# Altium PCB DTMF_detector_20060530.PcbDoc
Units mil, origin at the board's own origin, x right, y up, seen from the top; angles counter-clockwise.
Board outline 2118 x 2053 mil, 2 copper layers (Top Layer, Bottom Layer); 16 components, 31 nets, 85 pads, 0 vias.
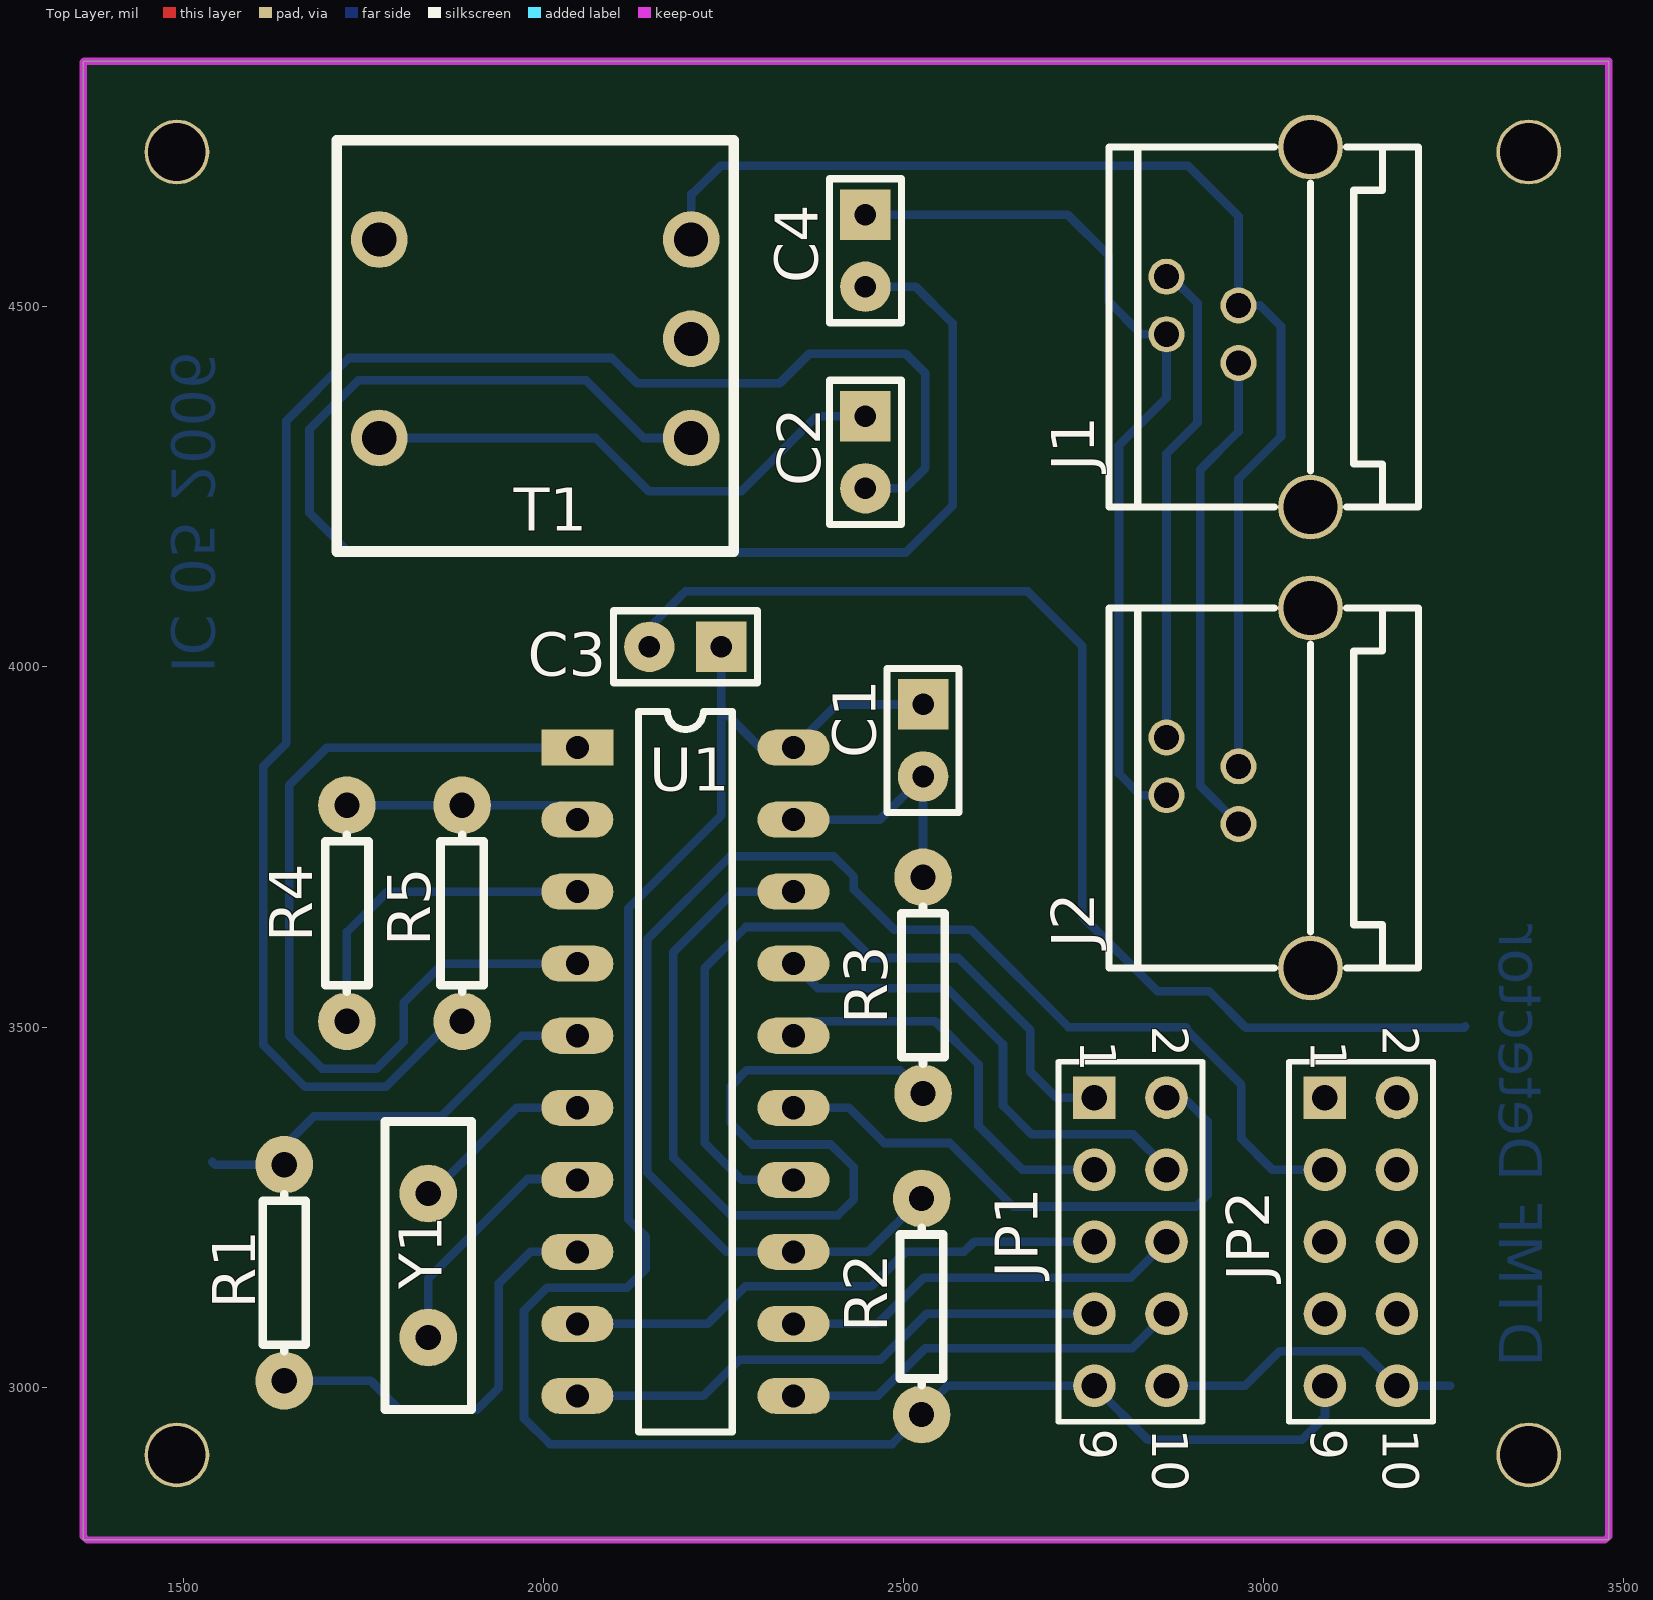
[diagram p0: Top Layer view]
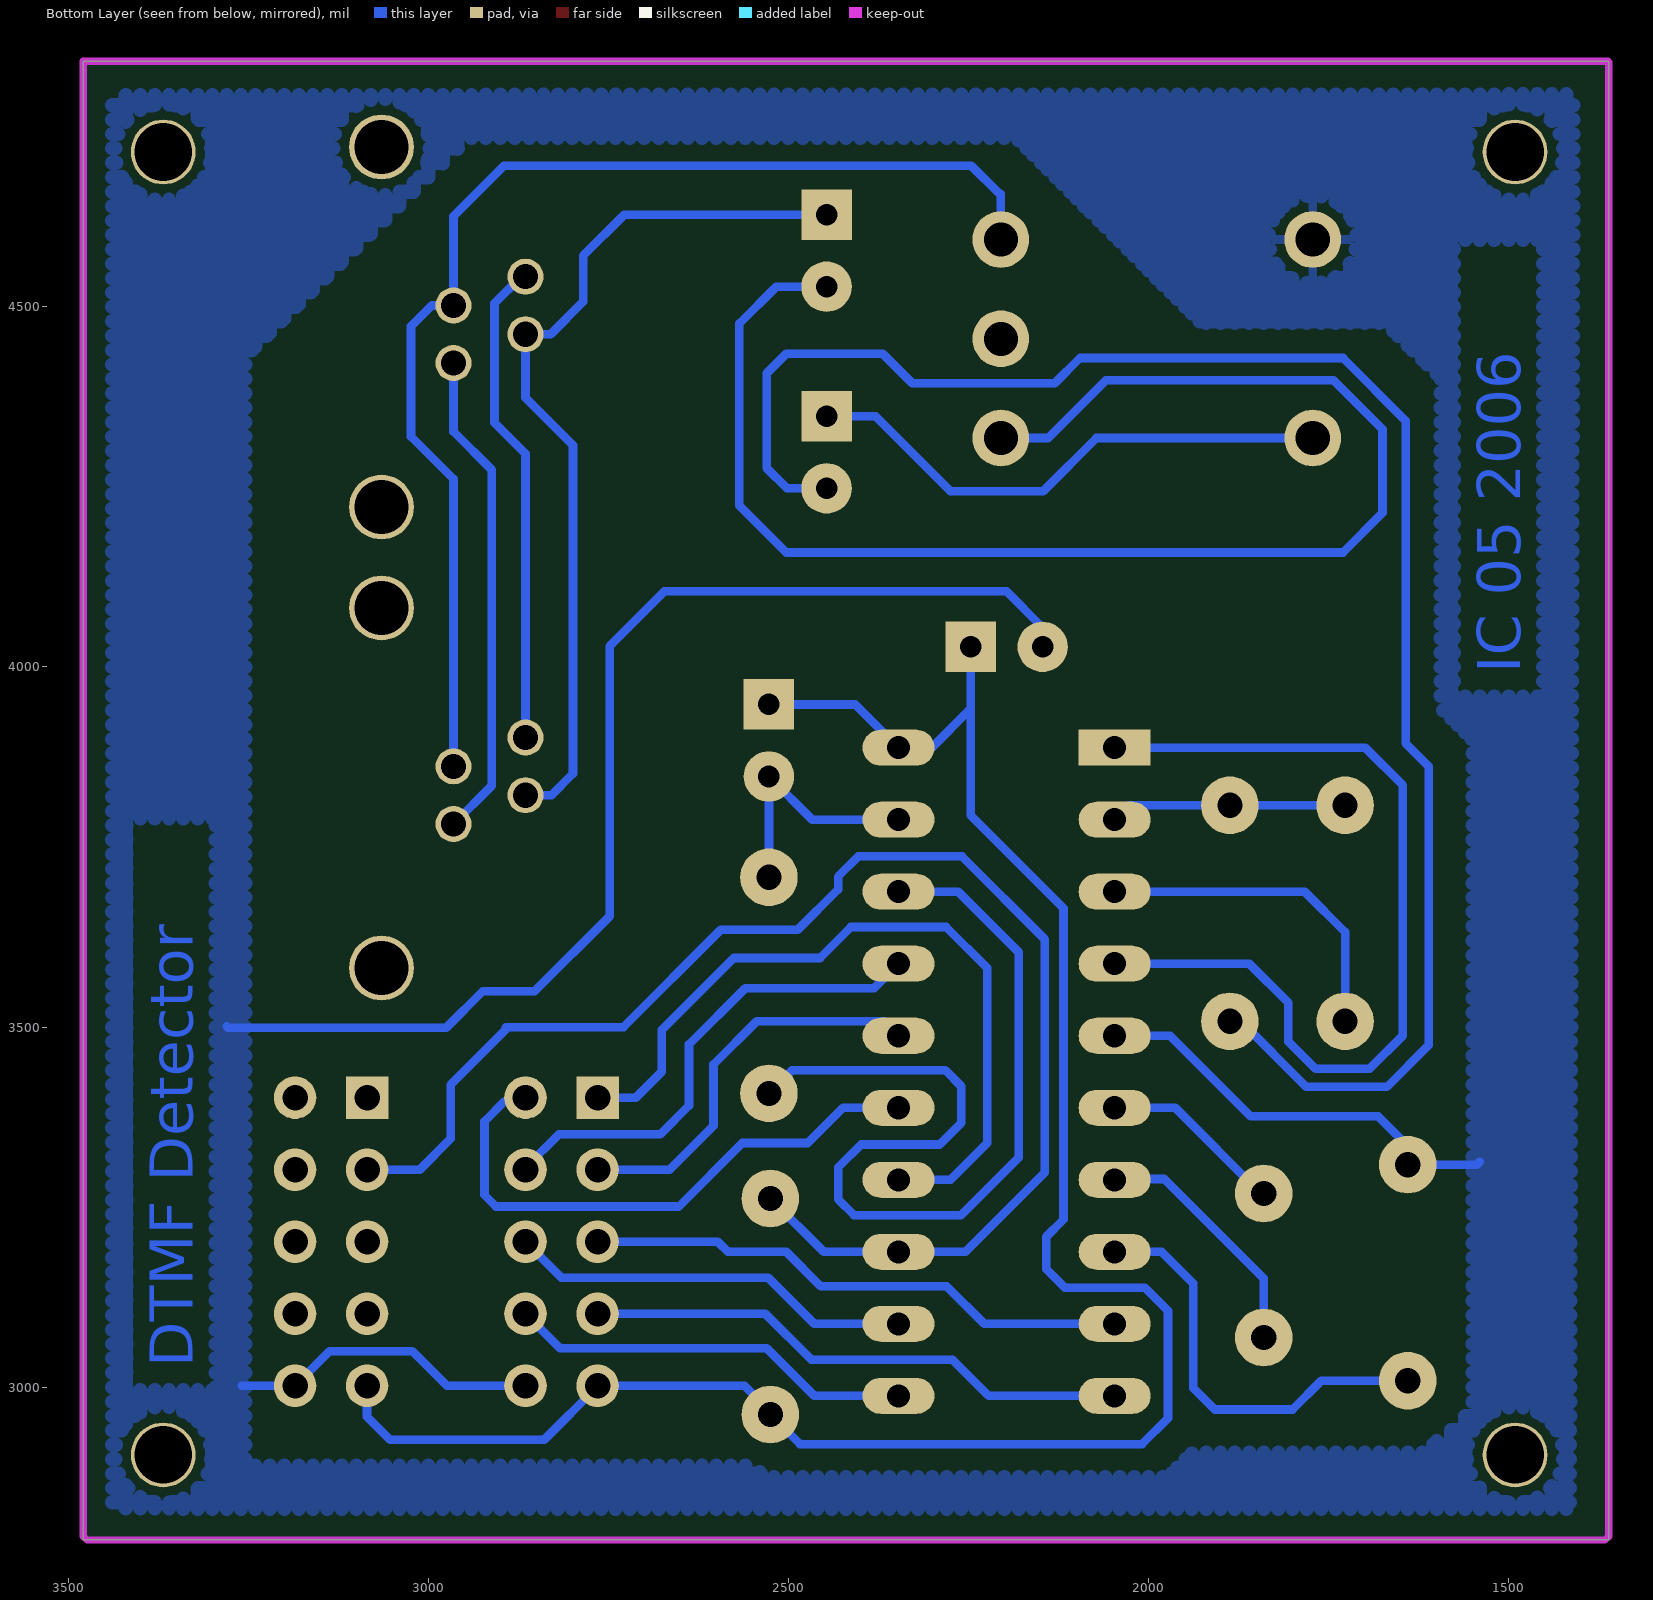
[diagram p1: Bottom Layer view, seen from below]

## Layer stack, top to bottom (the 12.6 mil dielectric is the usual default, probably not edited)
Top Layer: signal copper 1.4
Dielectric: dielectric 12.6, FR-4, Dk 4.8
Bottom Layer: signal copper 1.4

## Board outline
1362,4841 3479,4841 3479,2788 1361,2788 1361,4840

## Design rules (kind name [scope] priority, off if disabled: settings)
Clearance [All] p1: gap=12
ComponentClearance [All] p1: gap=10 collisioncheckmode=0
PlaneConnect [All] p1: planeconnectstyle=Relief reliefexpansion=20 reliefentries=4 reliefconductorwidth=12 reliefairgap=12
PolygonConnect [All] p1: connectstyle=Relief reliefconductorwidth=12 reliefentries=4 polygonreliefangle="90 Angle"
RoomDefinition DTMF_detector [InComponentClass('DTMF_detector')] p1: confinementstyle=ConfineIn formatcopy=TRUE outline 1363,2792 3480,2792 3480,4845 1363,4845
RoutingLayers [All] p1: top layer=Horizontal bottom layer=Vertical
RoutingVias [All] p1: holewidth=28 width=50 viastyle="Through Hole" minholewidth=28 minwidth=50 maxholewidth=28 maxwidth=50
SolderMaskExpansion [All] p1: expansion=4
TestPointUsage [All] p1: valid=0 allowmultiple=FALSE
Testpoint [All] p1: side=15 testpointundercomponent=TRUE minsize=40 maxsize=100 preferedsize=60 minholesize=0 maxholesize=40 preferedholesize=32 testpointgrid=1 style=1023 order=-539222988
Width [All] p1: maxlimit=20 minlimit=12 preferedwidth=15 bottomlayer_prefwidth=12 minimp=50.000000 maximp=50.000000 favimp=50.000000
15 further rules are at their usual default settings.

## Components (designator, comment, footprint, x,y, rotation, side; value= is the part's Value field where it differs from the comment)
C1 "100nF" "CAP Rec/0.1" 2527,3948 r90 top (schematic designator C2)
C2 "100nF" "CAP Rec/0.1" 2447,4348 r90 top (schematic designator C3)
C3 "100nF" "CAP Rec/0.1" 2247,4028 r0 top
C4 "470nF" "CAP Rec/0.1" 2447,4628 r90 top
J1 "RJ11" RJ11 2965,4322 r90 top
J2 "RJ11" RJ11 2965,3682 r90 top
JP1 "Header 5X2" HDR2X5 2765,3402 r270 top
JP2 "Header 5X2" HDR2X5 3085,3402 r270 top
R1 "10K" RES 1640,3309 r270 top
R2 "3K" RES 2525,3262 r270 top
R3 "374K" RES 2527,3408 r90 top
R4 "100K" RES 1727,3808 r270 top (schematic designator R5)
R5 "100K" RES 1887,3508 r90 top (schematic designator R6)
T1 "AX141A1" "TRAFO 1:1" 2205,4062 r180 top
U1 "CM8888PI" DIP20 2047,3888 r0 top
Y1 "3.579545 MHz" XTAL1 1840,3269 r270 top

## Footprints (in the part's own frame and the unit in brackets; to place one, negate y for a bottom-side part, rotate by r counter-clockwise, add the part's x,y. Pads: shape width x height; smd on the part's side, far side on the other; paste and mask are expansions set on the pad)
"CAP Rec/0.1" [mil]
  rect 70x70 hole 30: 1(0,0)
  round 70 hole 30: 2(-100,0)
  silkscreen extent -150,-50 50,50
DIP20 [mil]
  rect 100x50 hole 32: 1(0,0)
  oval 100x50 hole 32: 2(0,-100) 3(0,-200) 4(0,-300) 5(0,-400) 6(0,-500) 7(0,-600) 8(0,-700) 9(0,-800) 10(0,-900) 11(300,-900) 12(300,-800) 13(300,-700) 14(300,-600) 15(300,-500) 16(300,-400) 17(300,-300) 18(300,-200) 19(300,-100) 20(300,0)
  silkscreen extent 85,-950 215,50
HDR2X5 [mm]
  rect 1.5x1.5 hole 0.9: 1(0,0)
  round 1.5 hole 0.9: 2(0,2.54) 3(2.54,0) 4(2.54,2.54) 5(5.08,0) 6(5.08,2.54) 7(7.62,0) 8(7.62,2.54) 9(10.16,0) 10(10.16,2.54)
  silkscreen extent -1.27,-1.27 11.43,3.81
RES [mil]
  round 80 hole 35: 1(0,0) 2(300,0)
  silkscreen extent 41,-30 259,30
RJ11 [mil]
  round 50 hole 35: 1(100,0) 2(140,100) 3(180,0) 4(220,100)
  round 90 hole 75: 5(-100,-100) 6(400,-100)
  silkscreen extent -100,-250 400,180
"TRAFO 1:1" [mm]
  round 2 hole 1.2: 1(0,-6.5) 2(0,-10) 3(0,-13.5) 4(11,-13.5) 6(11,-6.5)
  silkscreen extent -1.5,-17 12.5,-2.5
XTAL1 [mil]
  round 80 hole 35: 1(0,0) 2(200,0)
  silkscreen extent -100,-60 300,60

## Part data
C1 C2 C3 C4: library part CAP, "Capacitor"
J1: library part CON1x2, "Connector"
J2: "Telephone Connector"
JP1 JP2: "Header, 5-Pin, Dual row"
R1 R2 R3 R4 R5: library part RES
T1: library part "Trans Cupl", "Transformer (Coupled Inductor Model)"
U1: "DTMF Transceiver"
Y1: library part XTAL1

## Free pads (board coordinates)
  round 90 hole 80: 0(1491,4715) 1(1491,4715) 2(1491,2906) 3(1491,2906) 4(3368,2906) 5(3368,2906) 6(3368,4715) 7(3368,4715)

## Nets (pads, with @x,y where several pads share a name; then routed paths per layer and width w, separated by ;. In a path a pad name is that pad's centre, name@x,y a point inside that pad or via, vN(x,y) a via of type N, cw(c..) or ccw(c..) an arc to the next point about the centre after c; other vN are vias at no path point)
D0: JP1.1 U1.14 | length 1083.9
  Bottom Layer w12: U1.14 2275,3288 2224,3339 2224,3582 2281,3639 2413,3639 2456,3596 2576,3596 2676,3496 2676,3438 2712,3402 JP1.1
D1: JP1.2 U1.15 | length 814
  Bottom Layer w12: U1.15 2424,3388 2473,3339 2564,3339 2652,3251 2906,3251 2922,3267 2922,3369 2894,3397 2865,3397 JP1.2
D2: JP1.3 U1.16 | length 561.4
  Bottom Layer w12: U1.16 2367,3508 2544,3508 2604,3448 2604,3363 2665,3302 JP1.3
D3: JP1.4 U1.17 | length 688
  Bottom Layer w12: U1.17 2381,3554 2560,3554 2638,3476 2638,3391 2678,3351 2819,3351 2865,3305 JP1.4
GND: C3.2 JP1.10 JP2.10 R1.1 T1.4 U1.5 | length 2684
  Bottom Layer w12: 1540,3313 1544,3309 R1.1 1640,3335 1681,3376 1858,3376 1970,3488 U1.5 ; C3.2 2147,4055 2197,4105 2672,4105 2748,4029 2748,3654 2852,3550 2924,3550 2975,3499 3278,3499 3280,3501 ; JP1.10 2974,3002 3022,3050 3137,3050 JP2.10 3259,3002
GS: R4.2 U1.3 | length 467.2
  Bottom Layer w12: R4.2 1727,3632 1783,3688 U1.3
IN-: R4.1 R5.2 U1.2 | length 328.3
  Bottom Layer w12: R4.1 2027,3808 U1.2
LINE1: C4.1 J1.2 J2.2 | length 1240
  Bottom Layer w12: C4.1 2728,4628 2785,4571 2785,4507 2830,4462 J1.2 2865,4374 2799,4308 2799,3852 2829,3822 J2.2
LINE2: J1.3 J2.3 T1.3 | length 1699.1
  Bottom Layer w12: T1.3 2205,4657 2207,4657 2246,4696 2895,4696 2965,4626 J1.3 2995,4502 3024,4473 3024,4320 2965,4261 J2.3
N_CS: JP1.7 U1.10 | length 765.2
  Bottom Layer w12: U1.10 2222,2988 2272,3038 2468,3038 2532,3102 JP1.7
N_IRQ: JP2.3 R2.1 U1.13 | length 2006.3
  Bottom Layer w12: R2.1 2451,3188 2254,3188 2144,3298 2144,3622 2259,3737 2403,3737 2431,3709 2431,3691 2487,3635 2594,3635 2729,3500 2892,3500 2892,3497 2969,3420 2969,3345 3012,3302 JP2.3
N_RD: JP1.6 U1.12 | length 565.2
  Bottom Layer w12: U1.12 2464,3088 2528,3152 2815,3152 JP1.6
N_WR: JP1.5 U1.9 | length 765.2
  Bottom Layer w12: U1.9 2228,3088 2280,3140 2455,3140 2503,3188 2584,3188 2598,3202 JP1.5
NetC1_2: C1.2 R3.2 U1.19 | length 344.9
  Bottom Layer w12: U1.19 2467,3788 C1.2 R3.2
NetC2_1: C2.1 T1.6 | length 748.8
  Bottom Layer w12: T1.6 2072.09,4317.91 2146,4244 2275,4244 2379,4348 C2.1
NetC2_2: C2.2 R5.1 | length 2410.3
  Bottom Layer w12: R5.1 1872,3508 1781,3417 1669,3417 1611,3475 1611,3862 1643,3894 1643,4342 1730,4429 2095,4429 2130,4394 2328,4394 2369,4435 2503,4435 2530,4408 2530,4276 2502,4248 C2.2
NetC4_2: C4.2 T1.1 | length 2045.2
  Bottom Layer w12: T1.1 2139.09,4317.91 2059,4398 1743,4398 1675,4330 1675,4214 1730,4159 2503,4159 2568,4224 2568,4477 2517,4528 C4.2
NetJ1_1: J1.1 J2.1 | length 683.9
  Bottom Layer w12: J2.1 2912,3835 2912,4274 2965,4327 J1.1
NetJ1_4: J1.4 J2.4 | length 679.1
  Bottom Layer w12: J2.4 2865,4296 2908,4339 2908,4505 2871,4542 J1.4
NetJP1_5: 
NetJP2_2: JP2.2
NetJP2_3: 
NetJP2_4: JP2.4
NetJP2_5: JP2.5
NetR1_2: R1.2 U1.8 | length 599.2
  Bottom Layer w12: R1.2 1760,3009 1800,2969 1908,2969 1938,2999 1938,3144 1982,3188 U1.8
NetR3_1: R3.1 U1.18 | length 1361.1
  Bottom Layer w12: U1.18 2264,3688 2180,3604 2180,3319 2260,3239 2409,3239 2431,3261 2431,3305 2399,3337 2290,3337 2260,3367 2260,3418 2282,3440 2495,3440 R3.1
OSC1: U1.6 Y1.1 | length 256.3
  Bottom Layer w12: Y1.1 1844,3269 1963,3388 U1.6
OSC2: U1.7 Y1.2 | length 346.6
  Bottom Layer w12: Y1.2 1840,3151 1978,3289 2046,3289 U1.7
RS0: JP1.8 U1.11 | length 565.2
  Bottom Layer w12: U1.11 2464,2988 2530,3054 2817,3054 JP1.8
VCC: C1.1 C3.1 JP1.9 JP2.9 R2.2 U1.20 | length 2847.3
  Bottom Layer w12: 2247,3942 2301,3888 U1.20 2407,3948 C1.1 ; C3.1 2247,3794 2118,3665 2118,3233 2142,3209 2142,3164 2116,3138 2005,3138 1973,3106 1973,2957 2009,2921 2484,2921 R2.2 2525,2966 2561,3002 JP1.9 2765,3001 2839,2927 3053,2927 3085,2959 JP2.9
VREF: U1.1 U1.4 | length 1334.7
  Bottom Layer w12: U1.4@2071,3588 1860,3588 1806,3534 1806,3480 1768,3442 1693,3442 1647,3488 1647,3836 1699,3888 U1.1@2077,3888
pads on no net: J1.5 J1.6 J2.5 J2.6 JP2.1 JP2.6 JP2.7 JP2.8 T1.2

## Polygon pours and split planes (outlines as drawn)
GND on Bottom Layer (hatched 90Degree grid 20 track 20): 1410,4795 3439,4794 3439,2832 3254,2831 3254,4431 2944,4735 2184,4735 1927,4478 1671,4478 1594,4401 1594,3943 1550,3899 1550,2970 1589,2931 1589,2831 1415,2831 1410,4777
GND on Bottom Layer (hatched 90Degree grid 20 track 20): 1589,2831 3254,2831 3254,2891 2549,2891 2533,2875 1973,2875 1939,2909 1616,2909 1597,2928 1597,2831

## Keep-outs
Keep-Out Layer:
  lines w10: 1361,4840 1361,2793 1366,2788 3474,2788 3479,2793 3479,4841 1362,4841

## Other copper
Bottom Layer:
  text "IC 05 2006" at 1484,3991 h60 r270
  text "DTMF Detector" at 3327,3028 h60 r270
